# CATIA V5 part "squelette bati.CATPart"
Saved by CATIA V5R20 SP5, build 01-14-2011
Part number: squelette bati
Bounding box of the stored display mesh (mm): x 0 to 10834.35, y -10000 to 10000, z 10472.604 to 12365.631
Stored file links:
  M:\EU_thinkMotion\IAO_2010\iao\IAO_MMS_Groupe1\Problemes\gduval\Gduval\train d'aterrissage squelette + piece kinematic\squelette bati.CATPart
  M:\EU_thinkMotion\IAO_2010\iao\IAO_MMS_Groupe1\Problemes\gduval\Gduval\train d'aterrissage squelette + piece kinematic\train d'aterrissage.CATProduct
  M:\EU_thinkMotion\IAO_2010\iao\IAO_MMS_Groupe1\Problemes\gduval\Gduval\train d'aterrissage squelette + piece kinematic\squelette de base.CATPart
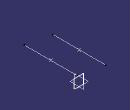
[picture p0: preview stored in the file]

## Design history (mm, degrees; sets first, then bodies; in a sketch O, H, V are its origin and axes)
Set1
  Plane1: linked copy from another document
  Point1: linked copy from another document
  Point2: linked copy from another document
Body1 (main body)
  Line1: type Normal, RefPoint Point1, RefSkin Plane1, Start -10000, End 10000
  Line2: type Normal, RefPoint Point2, RefSkin Plane1, Start -10000, End 10000
  Plane2: type Offset, RefPlane Plane1, Offset -200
